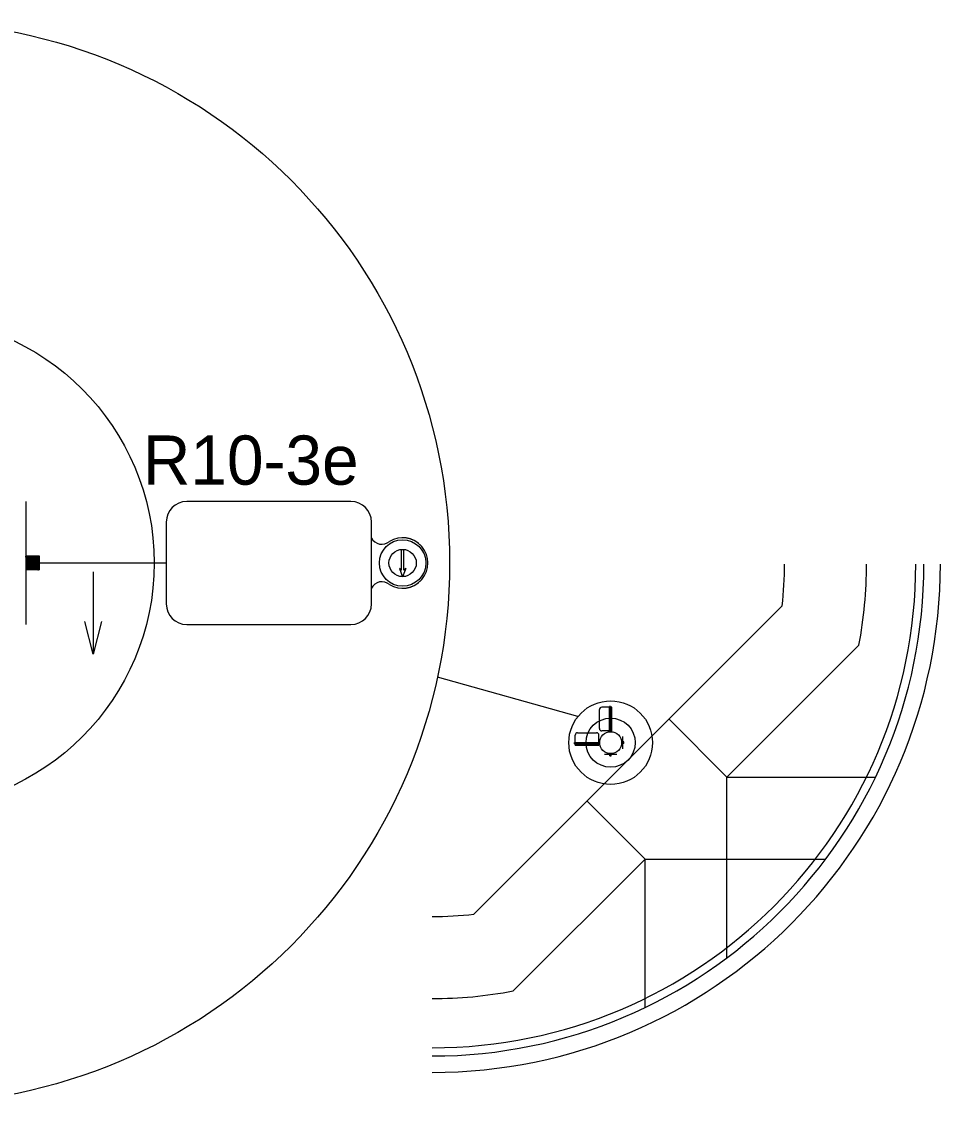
# Model space of a CAD drawing. Extents: x 1370050 to 1370716, y 380076 to 380502.
# Drawn here: x 1370568.5 to 1370624.6, y 380268.8 to 380334.9 of the extents above; entities that cross this region are included whole.
import ezdxf

# ---------------------------------------------------------------- set-up
doc = ezdxf.new("R2010")
doc.units = 0
doc.layers.add('T_Drafting', color=7, linetype='Continuous')

msp = doc.modelspace()

# ---------------------------------------------------------------- linework, layer by layer
at = {"layer": 'T_Drafting'}
for p, q in [((1370568.787, 380305.589), (1370568.787, 380298.089)), ((1370588.622, 380305.589), (1370578.606, 380305.589)), ((1370577.356, 380304.339), (1370577.356, 380299.339)), ((1370589.872, 380299.339), (1370589.872, 380304.339)), ((1370591.697, 380302.666), (1370591.847, 380302.666)), ((1370591.697, 380301.411), (1370591.697, 380302.666)), ((1370591.847, 380301.411), (1370591.847, 380302.666)), ((1370569.62, 380302.255), (1370568.787, 380302.255)), ((1370568.787, 380301.425), (1370569.617, 380302.255)), ((1370568.787, 380301.439), (1370569.603, 380302.255)), ((1370568.787, 380301.453), (1370569.589, 380302.255)), ((1370568.787, 380301.467), (1370569.575, 380302.255)), ((1370568.787, 380301.481), (1370569.561, 380302.255)), ((1370568.787, 380301.496), (1370569.546, 380302.255)), ((1370568.787, 380301.51), (1370569.532, 380302.255)), ((1370568.787, 380301.524), (1370569.518, 380302.255)), ((1370568.787, 380301.538), (1370569.504, 380302.255)), ((1370568.787, 380301.552), (1370569.49, 380302.255)), ((1370568.787, 380301.566), (1370569.476, 380302.255)), ((1370568.787, 380301.58), (1370569.462, 380302.255)), ((1370568.787, 380301.595), (1370569.447, 380302.255)), ((1370568.787, 380301.609), (1370569.433, 380302.255)), ((1370568.787, 380301.623), (1370569.419, 380302.255)), ((1370568.787, 380301.637), (1370569.405, 380302.255)), ((1370568.787, 380301.651), (1370569.391, 380302.255)), ((1370568.787, 380301.665), (1370569.377, 380302.255)), ((1370568.787, 380301.679), (1370569.363, 380302.255)), ((1370568.787, 380301.694), (1370569.348, 380302.255)), ((1370568.787, 380301.708), (1370569.334, 380302.255)), ((1370568.787, 380301.722), (1370569.32, 380302.255)), ((1370568.787, 380301.736), (1370569.306, 380302.255)), ((1370568.787, 380301.75), (1370569.292, 380302.255)), ((1370568.787, 380301.764), (1370569.278, 380302.255)), ((1370568.787, 380301.778), (1370569.264, 380302.255)), ((1370568.787, 380301.793), (1370569.249, 380302.255)), ((1370568.787, 380301.807), (1370569.235, 380302.255)), ((1370568.787, 380301.821), (1370569.221, 380302.255)), ((1370568.787, 380301.835), (1370569.207, 380302.255)), ((1370568.787, 380301.849), (1370569.193, 380302.255)), ((1370568.787, 380301.863), (1370569.179, 380302.255)), ((1370568.787, 380301.877), (1370569.165, 380302.255)), ((1370568.787, 380301.892), (1370569.15, 380302.255)), ((1370568.787, 380301.906), (1370569.136, 380302.255)), ((1370568.787, 380301.92), (1370569.122, 380302.255)), ((1370568.787, 380301.934), (1370569.108, 380302.255)), ((1370568.787, 380301.948), (1370569.094, 380302.255)), ((1370568.787, 380301.962), (1370569.08, 380302.255)), ((1370568.787, 380301.976), (1370569.066, 380302.255)), ((1370568.787, 380301.991), (1370569.051, 380302.255)), ((1370568.787, 380302.005), (1370569.037, 380302.255)), ((1370568.787, 380302.019), (1370569.023, 380302.255)), ((1370568.787, 380302.033), (1370569.009, 380302.255)), ((1370568.787, 380302.047), (1370568.995, 380302.255)), ((1370568.787, 380302.061), (1370568.981, 380302.255)), ((1370568.787, 380302.075), (1370568.967, 380302.255)), ((1370568.787, 380302.09), (1370568.952, 380302.255)), ((1370568.787, 380302.104), (1370568.938, 380302.255)), ((1370568.787, 380302.118), (1370568.924, 380302.255)), ((1370568.787, 380302.132), (1370568.91, 380302.255)), ((1370568.787, 380302.146), (1370568.896, 380302.255)), ((1370568.787, 380302.16), (1370568.882, 380302.255)), ((1370568.787, 380302.174), (1370568.868, 380302.255)), ((1370568.787, 380302.189), (1370568.853, 380302.255)), ((1370568.787, 380302.203), (1370568.839, 380302.255)), ((1370568.787, 380302.217), (1370568.825, 380302.255)), ((1370568.787, 380302.231), (1370568.811, 380302.255)), ((1370568.787, 380302.245), (1370568.797, 380302.255)), ((1370568.798, 380301.422), (1370569.62, 380302.244)), ((1370568.812, 380301.422), (1370569.62, 380302.23)), ((1370568.826, 380301.422), (1370569.62, 380302.216)), ((1370568.84, 380301.422), (1370569.62, 380302.202)), ((1370568.855, 380301.422), (1370569.62, 380302.188)), ((1370568.869, 380301.422), (1370569.62, 380302.173)), ((1370568.883, 380301.422), (1370569.62, 380302.159)), ((1370568.897, 380301.422), (1370569.62, 380302.145)), ((1370568.911, 380301.422), (1370569.62, 380302.131)), ((1370568.925, 380301.422), (1370569.62, 380302.117)), ((1370568.939, 380301.422), (1370569.62, 380302.103)), ((1370568.953, 380301.422), (1370569.62, 380302.089)), ((1370568.968, 380301.422), (1370569.62, 380302.074)), ((1370568.982, 380301.422), (1370569.62, 380302.06)), ((1370568.996, 380301.422), (1370569.62, 380302.046)), ((1370569.01, 380301.422), (1370569.62, 380302.032)), ((1370569.024, 380301.422), (1370569.62, 380302.018)), ((1370569.038, 380301.422), (1370569.62, 380302.004)), ((1370569.052, 380301.422), (1370569.62, 380301.99)), ((1370569.067, 380301.422), (1370569.62, 380301.975)), ((1370569.081, 380301.422), (1370569.62, 380301.961)), ((1370569.095, 380301.422), (1370569.62, 380301.947)), ((1370569.109, 380301.422), (1370569.62, 380301.933)), ((1370569.123, 380301.422), (1370569.62, 380301.919)), ((1370569.137, 380301.422), (1370569.62, 380301.905)), ((1370569.151, 380301.422), (1370569.62, 380301.891)), ((1370569.166, 380301.422), (1370569.62, 380301.876)), ((1370569.18, 380301.422), (1370569.62, 380301.862)), ((1370569.194, 380301.422), (1370569.62, 380301.848)), ((1370569.208, 380301.422), (1370569.62, 380301.834)), ((1370569.222, 380301.422), (1370569.62, 380301.82)), ((1370569.236, 380301.422), (1370569.62, 380301.806)), ((1370569.25, 380301.422), (1370569.62, 380301.792)), ((1370569.265, 380301.422), (1370569.62, 380301.777)), ((1370569.279, 380301.422), (1370569.62, 380301.763)), ((1370569.293, 380301.422), (1370569.62, 380301.749)), ((1370569.307, 380301.422), (1370569.62, 380301.735)), ((1370569.321, 380301.422), (1370569.62, 380301.721)), ((1370569.335, 380301.422), (1370569.62, 380301.707)), ((1370569.349, 380301.422), (1370569.62, 380301.693)), ((1370569.364, 380301.422), (1370569.62, 380301.678)), ((1370569.378, 380301.422), (1370569.62, 380301.664)), ((1370569.62, 380301.422), (1370569.62, 380302.255)), ((1370569.62, 380301.839), (1370577.356, 380301.839)), ((1370569.62, 380301.422), (1370568.787, 380301.422)), ((1370569.392, 380301.422), (1370569.62, 380301.65)), ((1370569.406, 380301.422), (1370569.62, 380301.636)), ((1370569.42, 380301.422), (1370569.62, 380301.622)), ((1370569.434, 380301.422), (1370569.62, 380301.608)), ((1370569.448, 380301.422), (1370569.62, 380301.594)), ((1370569.463, 380301.422), (1370569.62, 380301.579)), ((1370569.477, 380301.422), (1370569.62, 380301.565)), ((1370569.491, 380301.422), (1370569.62, 380301.551)), ((1370569.505, 380301.422), (1370569.62, 380301.537)), ((1370569.519, 380301.422), (1370569.62, 380301.523)), ((1370569.533, 380301.422), (1370569.62, 380301.509)), ((1370569.547, 380301.422), (1370569.62, 380301.495)), ((1370569.562, 380301.422), (1370569.62, 380301.48)), ((1370569.576, 380301.422), (1370569.62, 380301.466)), ((1370569.59, 380301.422), (1370569.62, 380301.452)), ((1370569.604, 380301.422), (1370569.62, 380301.438)), ((1370569.618, 380301.422), (1370569.62, 380301.424)), ((1370572.897, 380301.306), (1370572.897, 380296.273)), ((1370591.572, 380301.511), (1370591.772, 380301.005)), ((1370591.697, 380301.411), (1370591.572, 380301.511)), ((1370591.972, 380301.511), (1370591.772, 380301.005)), ((1370591.972, 380301.511), (1370591.847, 380301.411)), ((1370596.123, 380280.425), (1370614.916, 380299.217)), ((1370578.606, 380298.089), (1370588.622, 380298.089)), ((1370611.555, 380288.785), (1370619.604, 380296.834)), ((1370602.463, 380292.472), (1370593.893, 380294.874)), ((1370604.384, 380291.548), (1370604.384, 380293.09)), ((1370604.459, 380293.09), (1370604.384, 380293.09)), ((1370604.459, 380291.548), (1370604.459, 380293.09)), ((1370603.775, 380291.744), (1370603.775, 380292.894)), ((1370604.384, 380293.044), (1370603.925, 380293.044)), ((1370604.534, 380293.044), (1370604.459, 380293.044)), ((1370604.534, 380291.594), (1370604.534, 380293.044)), ((1370608.019, 380292.321), (1370611.555, 380288.785)), ((1370602.296, 380290.881), (1370602.296, 380291.34)), ((1370602.446, 380291.49), (1370603.596, 380291.49)), ((1370603.746, 380290.881), (1370603.746, 380291.34)), ((1370604.384, 380291.594), (1370603.925, 380291.594)), ((1370604.459, 380291.548), (1370604.384, 380291.548)), ((1370604.534, 380291.594), (1370604.459, 380291.594)), ((1370605.175, 380291.256), (1370605.175, 380290.506)), ((1370602.25, 380290.881), (1370603.792, 380290.881)), ((1370602.25, 380290.806), (1370602.25, 380290.881)), ((1370602.25, 380290.806), (1370603.792, 380290.806)), ((1370602.296, 380290.731), (1370602.296, 380290.806)), ((1370602.296, 380290.731), (1370603.746, 380290.731)), ((1370603.746, 380290.731), (1370603.746, 380290.806)), ((1370603.792, 380290.806), (1370603.792, 380290.881)), ((1370605.259, 380290.923), (1370605.175, 380290.923)), ((1370605.175, 380290.84), (1370605.258, 380290.923)), ((1370605.175, 380290.841), (1370605.257, 380290.923)), ((1370605.175, 380290.843), (1370605.256, 380290.923)), ((1370605.175, 380290.844), (1370605.254, 380290.923)), ((1370605.175, 380290.846), (1370605.253, 380290.923)), ((1370605.175, 380290.847), (1370605.251, 380290.923)), ((1370605.175, 380290.848), (1370605.25, 380290.923)), ((1370605.175, 380290.85), (1370605.249, 380290.923)), ((1370605.175, 380290.851), (1370605.247, 380290.923)), ((1370605.175, 380290.853), (1370605.246, 380290.923)), ((1370605.175, 380290.854), (1370605.244, 380290.923)), ((1370605.175, 380290.855), (1370605.243, 380290.923)), ((1370605.175, 380290.857), (1370605.242, 380290.923)), ((1370605.175, 380290.858), (1370605.24, 380290.923)), ((1370605.175, 380290.86), (1370605.239, 380290.923)), ((1370605.175, 380290.861), (1370605.237, 380290.923)), ((1370605.175, 380290.863), (1370605.236, 380290.923)), ((1370605.175, 380290.864), (1370605.234, 380290.923)), ((1370605.175, 380290.865), (1370605.233, 380290.923)), ((1370605.175, 380290.867), (1370605.232, 380290.923)), ((1370605.175, 380290.868), (1370605.23, 380290.923)), ((1370605.175, 380290.87), (1370605.229, 380290.923)), ((1370605.175, 380290.871), (1370605.227, 380290.923)), ((1370605.175, 380290.872), (1370605.226, 380290.923)), ((1370605.175, 380290.874), (1370605.225, 380290.923)), ((1370605.175, 380290.875), (1370605.223, 380290.923)), ((1370605.175, 380290.877), (1370605.222, 380290.923)), ((1370605.175, 380290.878), (1370605.22, 380290.923)), ((1370605.175, 380290.88), (1370605.219, 380290.923)), ((1370605.175, 380290.881), (1370605.217, 380290.923)), ((1370605.175, 380290.882), (1370605.216, 380290.923)), ((1370605.175, 380290.884), (1370605.215, 380290.923)), ((1370605.175, 380290.885), (1370605.213, 380290.923)), ((1370605.175, 380290.887), (1370605.212, 380290.923)), ((1370605.175, 380290.888), (1370605.21, 380290.923)), ((1370605.175, 380290.889), (1370605.209, 380290.923)), ((1370605.175, 380290.891), (1370605.208, 380290.923)), ((1370605.175, 380290.892), (1370605.206, 380290.923)), ((1370605.175, 380290.894), (1370605.205, 380290.923)), ((1370605.175, 380290.895), (1370605.203, 380290.923)), ((1370605.175, 380290.896), (1370605.202, 380290.923)), ((1370605.175, 380290.898), (1370605.2, 380290.923)), ((1370605.175, 380290.899), (1370605.199, 380290.923)), ((1370605.175, 380290.901), (1370605.198, 380290.923)), ((1370605.175, 380290.902), (1370605.196, 380290.923)), ((1370605.175, 380290.904), (1370605.195, 380290.923)), ((1370605.175, 380290.905), (1370605.193, 380290.923)), ((1370605.175, 380290.906), (1370605.192, 380290.923)), ((1370605.175, 380290.908), (1370605.191, 380290.923)), ((1370605.175, 380290.909), (1370605.189, 380290.923)), ((1370605.175, 380290.911), (1370605.188, 380290.923)), ((1370605.175, 380290.912), (1370605.186, 380290.923)), ((1370605.175, 380290.913), (1370605.185, 380290.923)), ((1370605.175, 380290.915), (1370605.184, 380290.923)), ((1370605.175, 380290.916), (1370605.182, 380290.923)), ((1370605.175, 380290.918), (1370605.181, 380290.923)), ((1370605.175, 380290.919), (1370605.179, 380290.923)), ((1370605.175, 380290.921), (1370605.178, 380290.923)), ((1370605.175, 380290.922), (1370605.176, 380290.923)), ((1370605.259, 380290.84), (1370605.175, 380290.84)), ((1370605.177, 380290.84), (1370605.259, 380290.922)), ((1370605.178, 380290.84), (1370605.259, 380290.92)), ((1370605.179, 380290.84), (1370605.259, 380290.919)), ((1370605.181, 380290.84), (1370605.259, 380290.918)), ((1370605.182, 380290.84), (1370605.259, 380290.916)), ((1370605.184, 380290.84), (1370605.259, 380290.915)), ((1370605.185, 380290.84), (1370605.259, 380290.913)), ((1370605.186, 380290.84), (1370605.259, 380290.912)), ((1370605.188, 380290.84), (1370605.259, 380290.911)), ((1370605.189, 380290.84), (1370605.259, 380290.909)), ((1370605.191, 380290.84), (1370605.259, 380290.908)), ((1370605.192, 380290.84), (1370605.259, 380290.906)), ((1370605.194, 380290.84), (1370605.259, 380290.905)), ((1370605.195, 380290.84), (1370605.259, 380290.903)), ((1370605.196, 380290.84), (1370605.259, 380290.902)), ((1370605.198, 380290.84), (1370605.259, 380290.901)), ((1370605.199, 380290.84), (1370605.259, 380290.899)), ((1370605.201, 380290.84), (1370605.259, 380290.898)), ((1370605.202, 380290.84), (1370605.259, 380290.896)), ((1370605.203, 380290.84), (1370605.259, 380290.895)), ((1370605.205, 380290.84), (1370605.259, 380290.894)), ((1370605.206, 380290.84), (1370605.259, 380290.892)), ((1370605.208, 380290.84), (1370605.259, 380290.891)), ((1370605.209, 380290.84), (1370605.259, 380290.889)), ((1370605.21, 380290.84), (1370605.259, 380290.888)), ((1370605.212, 380290.84), (1370605.259, 380290.886)), ((1370605.213, 380290.84), (1370605.259, 380290.885)), ((1370605.215, 380290.84), (1370605.259, 380290.884)), ((1370605.216, 380290.84), (1370605.259, 380290.882)), ((1370605.218, 380290.84), (1370605.259, 380290.881)), ((1370605.219, 380290.84), (1370605.259, 380290.879)), ((1370605.22, 380290.84), (1370605.259, 380290.878)), ((1370605.222, 380290.84), (1370605.259, 380290.877)), ((1370605.223, 380290.84), (1370605.259, 380290.875)), ((1370605.225, 380290.84), (1370605.259, 380290.874)), ((1370605.226, 380290.84), (1370605.259, 380290.872)), ((1370605.227, 380290.84), (1370605.259, 380290.871)), ((1370605.229, 380290.84), (1370605.259, 380290.87)), ((1370605.23, 380290.84), (1370605.259, 380290.868)), ((1370605.232, 380290.84), (1370605.259, 380290.867)), ((1370605.233, 380290.84), (1370605.259, 380290.865)), ((1370605.235, 380290.84), (1370605.259, 380290.864)), ((1370605.236, 380290.84), (1370605.259, 380290.862)), ((1370605.237, 380290.84), (1370605.259, 380290.861)), ((1370605.239, 380290.84), (1370605.259, 380290.86)), ((1370605.24, 380290.84), (1370605.259, 380290.858)), ((1370605.242, 380290.84), (1370605.259, 380290.857)), ((1370605.243, 380290.84), (1370605.259, 380290.855)), ((1370605.244, 380290.84), (1370605.259, 380290.854)), ((1370605.246, 380290.84), (1370605.259, 380290.853)), ((1370605.247, 380290.84), (1370605.259, 380290.851)), ((1370605.249, 380290.84), (1370605.259, 380290.85)), ((1370605.25, 380290.84), (1370605.259, 380290.848)), ((1370605.252, 380290.84), (1370605.259, 380290.847)), ((1370605.253, 380290.84), (1370605.259, 380290.845)), ((1370605.254, 380290.84), (1370605.259, 380290.844)), ((1370605.256, 380290.84), (1370605.259, 380290.843)), ((1370605.257, 380290.84), (1370605.259, 380290.841)), ((1370605.259, 380290.84), (1370605.259, 380290.923)), ((1370605.259, 380290.84), (1370605.259, 380290.84)), ((1370604.834, 380290.165), (1370604.084, 380290.165)), ((1370604.417, 380290.081), (1370604.417, 380290.165)), ((1370604.417, 380290.082), (1370604.5, 380290.165)), ((1370604.417, 380290.083), (1370604.498, 380290.165)), ((1370604.417, 380290.085), (1370604.497, 380290.165)), ((1370604.417, 380290.086), (1370604.496, 380290.165)), ((1370604.417, 380290.088), (1370604.494, 380290.165)), ((1370604.417, 380290.089), (1370604.493, 380290.165)), ((1370604.417, 380290.09), (1370604.491, 380290.165)), ((1370604.417, 380290.092), (1370604.49, 380290.165)), ((1370604.417, 380290.093), (1370604.489, 380290.165)), ((1370604.417, 380290.095), (1370604.487, 380290.165)), ((1370604.417, 380290.096), (1370604.486, 380290.165)), ((1370604.417, 380290.097), (1370604.484, 380290.165)), ((1370604.417, 380290.099), (1370604.483, 380290.165)), ((1370604.417, 380290.1), (1370604.481, 380290.165)), ((1370604.417, 380290.102), (1370604.48, 380290.165)), ((1370604.417, 380290.103), (1370604.479, 380290.165)), ((1370604.417, 380290.105), (1370604.477, 380290.165)), ((1370604.417, 380290.106), (1370604.476, 380290.165)), ((1370604.417, 380290.107), (1370604.474, 380290.165)), ((1370604.417, 380290.109), (1370604.473, 380290.165)), ((1370604.417, 380290.11), (1370604.472, 380290.165)), ((1370604.417, 380290.112), (1370604.47, 380290.165)), ((1370604.417, 380290.113), (1370604.469, 380290.165)), ((1370604.417, 380290.114), (1370604.467, 380290.165)), ((1370604.417, 380290.116), (1370604.466, 380290.165)), ((1370604.417, 380290.117), (1370604.464, 380290.165)), ((1370604.417, 380290.119), (1370604.463, 380290.165)), ((1370604.417, 380290.12), (1370604.462, 380290.165)), ((1370604.417, 380290.121), (1370604.46, 380290.165)), ((1370604.417, 380290.123), (1370604.459, 380290.165)), ((1370604.417, 380290.124), (1370604.457, 380290.165)), ((1370604.417, 380290.126), (1370604.456, 380290.165)), ((1370604.417, 380290.127), (1370604.455, 380290.165)), ((1370604.417, 380290.129), (1370604.453, 380290.165)), ((1370604.417, 380290.13), (1370604.452, 380290.165)), ((1370604.417, 380290.131), (1370604.45, 380290.165)), ((1370604.417, 380290.133), (1370604.449, 380290.165)), ((1370604.417, 380290.134), (1370604.448, 380290.165)), ((1370604.417, 380290.136), (1370604.446, 380290.165)), ((1370604.417, 380290.137), (1370604.445, 380290.165)), ((1370604.417, 380290.138), (1370604.443, 380290.165)), ((1370604.417, 380290.14), (1370604.442, 380290.165)), ((1370604.417, 380290.141), (1370604.44, 380290.165)), ((1370604.417, 380290.143), (1370604.439, 380290.165)), ((1370604.417, 380290.144), (1370604.438, 380290.165)), ((1370604.417, 380290.146), (1370604.436, 380290.165)), ((1370604.417, 380290.147), (1370604.435, 380290.165)), ((1370604.417, 380290.148), (1370604.433, 380290.165)), ((1370604.417, 380290.15), (1370604.432, 380290.165)), ((1370604.417, 380290.151), (1370604.431, 380290.165)), ((1370604.417, 380290.153), (1370604.429, 380290.165)), ((1370604.417, 380290.154), (1370604.428, 380290.165)), ((1370604.417, 380290.155), (1370604.426, 380290.165)), ((1370604.417, 380290.157), (1370604.425, 380290.165)), ((1370604.417, 380290.158), (1370604.423, 380290.165)), ((1370604.417, 380290.16), (1370604.422, 380290.165)), ((1370604.417, 380290.161), (1370604.421, 380290.165)), ((1370604.417, 380290.163), (1370604.419, 380290.165)), ((1370604.417, 380290.164), (1370604.418, 380290.165)), ((1370604.417, 380290.081), (1370604.5, 380290.081)), ((1370604.418, 380290.081), (1370604.5, 380290.164)), ((1370604.419, 380290.081), (1370604.5, 380290.162)), ((1370604.421, 380290.081), (1370604.5, 380290.161)), ((1370604.422, 380290.081), (1370604.5, 380290.16)), ((1370604.424, 380290.081), (1370604.5, 380290.158)), ((1370604.425, 380290.081), (1370604.5, 380290.157)), ((1370604.426, 380290.081), (1370604.5, 380290.155)), ((1370604.428, 380290.081), (1370604.5, 380290.154)), ((1370604.429, 380290.081), (1370604.5, 380290.153)), ((1370604.431, 380290.081), (1370604.5, 380290.151)), ((1370604.432, 380290.081), (1370604.5, 380290.15)), ((1370604.433, 380290.081), (1370604.5, 380290.148)), ((1370604.435, 380290.081), (1370604.5, 380290.147)), ((1370604.436, 380290.081), (1370604.5, 380290.145)), ((1370604.438, 380290.081), (1370604.5, 380290.144)), ((1370604.439, 380290.081), (1370604.5, 380290.143)), ((1370604.441, 380290.081), (1370604.5, 380290.141)), ((1370604.442, 380290.081), (1370604.5, 380290.14)), ((1370604.443, 380290.081), (1370604.5, 380290.138)), ((1370604.445, 380290.081), (1370604.5, 380290.137)), ((1370604.446, 380290.081), (1370604.5, 380290.136)), ((1370604.448, 380290.081), (1370604.5, 380290.134)), ((1370604.449, 380290.081), (1370604.5, 380290.133)), ((1370604.45, 380290.081), (1370604.5, 380290.131)), ((1370604.452, 380290.081), (1370604.5, 380290.13)), ((1370604.453, 380290.081), (1370604.5, 380290.128)), ((1370604.455, 380290.081), (1370604.5, 380290.127)), ((1370604.456, 380290.081), (1370604.5, 380290.126)), ((1370604.458, 380290.081), (1370604.5, 380290.124)), ((1370604.459, 380290.081), (1370604.5, 380290.123)), ((1370604.46, 380290.081), (1370604.5, 380290.121)), ((1370604.462, 380290.081), (1370604.5, 380290.12)), ((1370604.463, 380290.081), (1370604.5, 380290.119)), ((1370604.465, 380290.081), (1370604.5, 380290.117)), ((1370604.466, 380290.081), (1370604.5, 380290.116)), ((1370604.467, 380290.081), (1370604.5, 380290.114)), ((1370604.469, 380290.081), (1370604.5, 380290.113)), ((1370604.47, 380290.081), (1370604.5, 380290.111)), ((1370604.472, 380290.081), (1370604.5, 380290.11)), ((1370604.473, 380290.081), (1370604.5, 380290.109)), ((1370604.474, 380290.081), (1370604.5, 380290.107)), ((1370604.476, 380290.081), (1370604.5, 380290.106)), ((1370604.477, 380290.081), (1370604.5, 380290.104)), ((1370604.479, 380290.081), (1370604.5, 380290.103)), ((1370604.48, 380290.081), (1370604.5, 380290.102)), ((1370604.482, 380290.081), (1370604.5, 380290.1)), ((1370604.483, 380290.081), (1370604.5, 380290.099)), ((1370604.484, 380290.081), (1370604.5, 380290.097)), ((1370604.486, 380290.081), (1370604.5, 380290.096)), ((1370604.487, 380290.081), (1370604.5, 380290.095)), ((1370604.489, 380290.081), (1370604.5, 380290.093)), ((1370604.49, 380290.081), (1370604.5, 380290.092)), ((1370604.491, 380290.081), (1370604.5, 380290.09)), ((1370604.493, 380290.081), (1370604.5, 380290.089)), ((1370604.494, 380290.081), (1370604.5, 380290.087)), ((1370604.496, 380290.081), (1370604.5, 380290.086)), ((1370604.497, 380290.081), (1370604.5, 380290.085)), ((1370604.499, 380290.081), (1370604.5, 380290.083)), ((1370604.5, 380290.081), (1370604.5, 380290.165)), ((1370604.5, 380290.081), (1370604.5, 380290.082)), ((1370611.555, 380277.762), (1370611.555, 380288.785)), ((1370611.555, 380288.785), (1370620.611, 380288.785)), ((1370603.019, 380287.321), (1370606.555, 380283.785)), ((1370598.506, 380275.736), (1370606.555, 380283.785)), ((1370606.555, 380283.785), (1370617.578, 380283.785)), ((1370606.555, 380274.729), (1370606.555, 380283.785))]:
    msp.add_line(p, q, dxfattribs=at)
msp.add_lwpolyline([(1370573.397, 380298.273), (1370572.897, 380296.273), (1370572.397, 380298.273)], dxfattribs=at)
for centre, radius in [((1370561.62, 380301.839), 33.016), ((1370561.62, 380301.839), 15), ((1370591.772, 380301.839), 1.417), ((1370591.772, 380301.839), 0.833), ((1370604.459, 380290.881), 2.552), ((1370604.459, 380290.881), 1.5), ((1370604.459, 380290.881), 0.667)]:
    msp.add_circle(centre, radius, dxfattribs=at)
for centre, radius, start, end in [((1370578.606, 380304.339), 1.25, 90, 180), ((1370588.622, 380304.339), 1.25, 0, 90), ((1370590.505, 380303.678), 0.7, 205.19558, 311.80279), ((1370591.772, 380301.839), 1.542, 238.74024, 121.25976), ((1370591.772, 380301.839), 1.542, 42.50664, 121.25976), ((1370593.568, 380301.772), 30, 270, 0), ((1370593.568, 380301.772), 31, 270, 0), ((1370593.568, 380301.772), 29.5, 270, 0), ((1370593.568, 380301.772), 21.5, 353.17407, 360), ((1370593.568, 380301.772), 26.5, 349.26033, 0), ((1370590.505, 380299.999), 0.7, 48.19721, 154.80442), ((1370591.772, 380301.839), 1.542, 238.74024, 317.49336), ((1370578.606, 380299.339), 1.25, 180, 270), ((1370588.622, 380299.339), 1.25, 270, 0), ((1370603.925, 380292.894), 0.15, 90, 180), ((1370602.446, 380291.34), 0.15, 90, 180), ((1370603.596, 380291.34), 0.15, 360, 90), ((1370603.925, 380291.744), 0.15, 180, 270), ((1370593.568, 380301.772), 21.5, 270, 276.82593), ((1370593.568, 380301.772), 26.5, 270, 280.73967)]:
    msp.add_arc(centre, radius, start, end, dxfattribs=at)

# ---------------------------------------------------------------- texts
msp.add_text('R10-3e', height=3, dxfattribs=at).set_placement((1370575.931, 380306.615))

doc.saveas('drawing.dxf')
